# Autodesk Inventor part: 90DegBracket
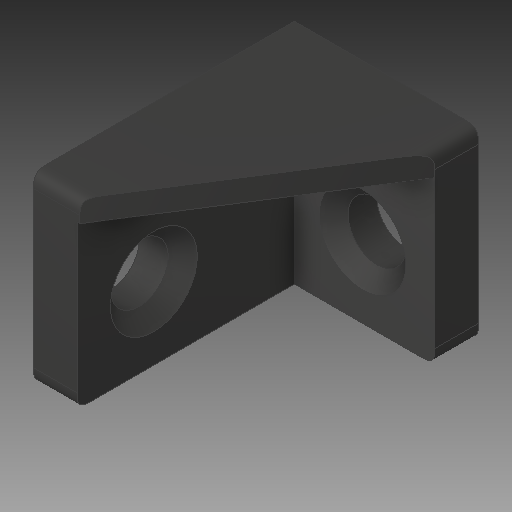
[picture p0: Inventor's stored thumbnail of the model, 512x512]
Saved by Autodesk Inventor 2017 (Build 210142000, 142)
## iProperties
Created: 2017-05
Part Number: 90DegBracket
Material: Generic
Document SubType Name: Modeling
Designer: Savy
Density: 1 g/cm^3
Appearance: Default
Author: Savy
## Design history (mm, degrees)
feature "Base1"
body "Solid1"
